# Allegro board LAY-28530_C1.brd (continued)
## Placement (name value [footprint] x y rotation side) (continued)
Q5  FDD4243  [TO252AA]  94.67 105.84 90 top
Q6  FDD4243  [TO252AA]  82.35 105.2 0 top
Q7  NTMD6N02R2  [SO8]  175.57 89.33 270 top
Q8  MMBT4401L  [SOT23]  175.19 43.36 180 top
Q9  MMBT4401L  [SOT23]  179 43.36 180 top
Q10  MMBT4401L  [SOT23]  203.76 31.93 180 top
Q11  MMBT4401L  [SOT23]  207.7 31.93 180 top
Q12  MMBT4401L  [SOT23]  199.57 21 0 top
Q13  MMBT4401L  [SOT23]  197.92 12.62 180 top
Q14  MMBT4401L  [SOT23]  211.89 146.61 0 bottom
Q15  MMBT4401L  [SOT23]  206.69 146.61 0 bottom
Q16  MMBT4401L  [SOT23]  194.75 141.15 180 bottom
Q17  MMBT3906L  [SOT23]  76.49 121.21 0 bottom
Q18  MMBT3904LT1G  [SOT23]  80.07 121.21 0 bottom
Q19  NTMD6N02R2  [SO8]  70.03 102.54 90 top
Q20  MMBT4401L  [SOT23]  71.56 109.14 0 top
Q21  NTMD6N02R2  [SO8]  175.19 100.38 90 bottom
Q22  NTMD6N02R2  [SO8]  175.57 87.81 90 bottom
Q23  IRLML6346TRPbF  [SOT23-40X40]  77.27 51.36 270 top
Q24  MMBT4401L  [SOT23]  179 43.36 180 bottom
Q25  MMBT4401L  [SOT23]  175.19 43.36 180 bottom
Q28  MMBT4401L  [SOT23]  158.68 8.18 270 bottom
Q29  MMBT4401L  [SOT23]  199.57 30.27 0 top
Q30  MMBT4401L  [SOT23]  199.57 26.08 0 top
R1  29.4K  [RC0603_OV]  80.57 153.97 180 bottom
R2  3.01K  [RC0603_OV]  80.57 155.75 0 bottom
R3  38.3K  [RC0603_OV]  84.26 158.8 90 top
R4  100K  [RC0603_OV]  86.04 158.8 90 top
R5  10.0K  [RC0603_OV]  68.38 155.75 0 top
R6  4.7K  [RC0402_25]  171.38 154.23 180 top
R7  4.7K  [RC0402_25]  171.38 153.08 180 top
R8  4.7K  [RC0402_25]  207.7 149.78 270 top
R9  1K  [RC0603_OV]  211.13 149.53 0 top
R10  18.2K  [RC0603_OV]  198.81 149.4 180 top
R11  51.1K  [RC0603_OV]  202.11 149.4 180 top
R13  0.033  [RC1206_OV]  84.26 147.62 180 top
R14  0  [RC0603_OV]  88.45 148.13 270 top
R15  10K  [RC0603_OV]  206.94 143.56 180 top
R16  1K  [RC0603_OV]  210.11 143.56 0 top
R17  4.7K  [RC0402_25]  213.42 143.56 180 top
R19  26.7K  [RC0603_OV]  191.06 141.91 0 top
R20  2.0K  [RC0603_OV]  159.44 141.02 270 top
R21  0  [RC0603_OV]  161.22 141.02 90 top
R22  0  [RC0603_OV]  193.99 141.02 90 top
R23  1K  [RC0603_OV]  195.64 141.02 90 top
R24  100  [RC0603_OV]  163.38 140.89 90 top
R25  1K  [RC0603_OV]  191.06 140.26 0 top
R26  100  [RC0603_OV]  143.19 139.88 90 top
R27  0  [RC0603_OV]  97.34 137.59 180 top
R28  2.49K  [RC0603_OV]  130.36 137.46 180 top
R29  4.7K  [RC0402_25]  196.53 137.46 180 top
R30  2.49K  [RC0603_OV]  109.78 137.34 180 top
R31  330  [RC0603_OV]  113.72 137.34 90 top
R32  330  [RC0603_OV]  138.87 137.34 90 top
R33  0  [RC0402_25]  193.35 136.95 180 top
R34  330  [RC0603_OV]  94.67 136.83 90 top
R35  330  [RC0603_OV]  118.42 136.19 0 top
R36  10.0K  [RC0603_OV]  196.78 136.07 180 top
R37  0  [RC0603_OV]  97.34 135.94 180 top
R38  0  [RC0402_25]  193.35 135.81 180 top
R39  1.0M  [RC0603_OV]  129.85 135.05 90 top
R40  1.0M  [RC0603_OV]  108.39 134.92 90 top
R42  15  [RC1206_OV]  92.64 124.13 90 bottom
R43  0  [RC0603_OV]  118.42 134.67 180 top
R44  36K  [RC0402_25]  196.4 134.54 180 top
R45  0  [RC0402_25]  196.4 133.4 0 top
R46  0  [RC0603_OV]  118.42 133.14 180 top
R47  0  [RC0603_OV]  81.84 115.36 180 bottom
R48  56K  [RC0402_25]  196.4 132.26 180 top
R49  0  [RC0402_25]  96.7 132 180 top
R50  33  [RC0603_OV]  108.77 131.62 0 top
R51  4.7K  [RC0603_OV]  118.93 131.37 0 top
R52  0  [RC0603_OV]  171.38 131.11 180 top
R53  0  [RC0402_25]  96.7 130.99 180 top
R54  0  [RC0402_25]  196.4 130.99 0 top
R55  0  [RC0402_25]  96.7 129.97 180 top
R56  4.7K  [RC0603_OV]  118.93 129.84 180 top
R57  4.7K  [RC0603_OV]  113.21 129.46 0 top
R58  4.7K  [RC0603_OV]  132.14 129.33 0 top
R59  0  [RC0402_25]  98.1 129.08 180 top
R60  100K  [RC0603_OV]  193.35 128.83 0 top
R61  0  [RC0603_OV]  81.84 113.46 180 bottom
R62  0  [RC0402_25]  98.1 128.06 180 top
R63  4.7K  [RC0603_OV]  113.21 127.81 180 top
R64  0  [RC0603_OV]  132.14 127.81 0 top
R65  0  [RC0402_25]  101.28 127.3 270 top
R66  0  [RC0603_OV]  108.77 127.05 0 top
R67  4.7K  [RC0603_OV]  124.14 126.79 270 top
R68  4.7K  [RC0603_OV]  122.48 126.67 90 top
R69  4.7K  [RC0603_OV]  120.83 126.67 270 top
R70  4.7K  [RC0603_OV]  113.21 126.16 0 top
R71  0  [RC0603_OV]  132.14 126.16 0 top
R72  4.7K  [RC0603_OV]  98.1 125.65 90 top
R73  4.7K  [RC0603_OV]  99.75 125.65 90 top
R74  0  [RC0603_OV]  108.77 125.4 0 top
R75  4.7K  [RC0603_OV]  174.17 125.14 270 top
R76  4.7K  [RC0603_OV]  174.17 121.59 90 top
R77  14K  [RC0402_25]  210.88 121.08 0 top
R78  100K  [RC0603_OV]  205.54 119.56 90 top
R79  100K  [RC0603_OV]  207.19 119.56 90 top
R80  0  [RC0402_25]  210.88 118.67 0 top
R81  24K  [RC0603_OV]  211.13 117.14 0 top
R82  10K  [RC0603_OV]  211.13 115.49 180 top
R83  100K  [RC0603_OV]  140.65 114.48 180 top
R84  1K  [RC0603_OV]  111.31 105.2 270 top
R85  191K  [RC0402_25]  134.17 114.09 0 top
R86  4.7K  [RC0402_25]  108.13 115.62 270 top
R87  20K  [RC0402_25]  134.17 112.95 180 top
R88  20K  [RC0402_25]  140.9 112.95 180 top
R89  100K  [RC0603_OV]  210.62 112.57 180 top
R90  0  [RC0402_25]  210.37 111.17 0 top
R91  10.0  [RC0402_25]  202.75 111.05 0 top
R92  0  [RC0402_25]  210.37 110.03 180 top
R93  100K  [RC0603_OV]  210.62 108.38 0 top
R94  10.0K  [RC0603_OV]  103.18 106.22 90 top
R95  10.0K  [RC0603_OV]  133.79 104.06 270 top
R96  10.0K  [RC0603_OV]  135.31 104.06 90 top
R97  10.0K  [RC0603_OV]  79.3 97.97 180 top
R98  330  [RC0402_25]  178.87 98.09 270 top
R99  22  [RC0603_OV]  166.3 96.82 0 top
R100  0.001  [RC1206_OV]  100.39 93.77 0 top
R101  330  [RC0402_25]  180.27 95.43 90 top
R102  2.2K  [RC0603_OV]  75.62 95.93 270 top
R104  10K  [RC0603_OV]  94.04 84.76 0 top
R105  10K  [RC0603_OV]  97.08 84.76 180 top
R106  33  [RC0603_OV]  103.05 85.77 0 top
R107  49.9  [RC0603_OV]  105.97 85.77 0 top
R108  33  [RC0603_OV]  103.05 83.61 0 top
R109  49.9  [RC0603_OV]  105.97 83.61 0 top
R110  33  [RC0603_OV]  103.05 81.71 0 top
R111  49.9  [RC0603_OV]  105.97 81.71 0 top
R112  1M  [RC0402_25]  93.53 80.31 270 top
R113  33  [RC0603_OV]  103.05 79.55 0 top
R114  49.9  [RC0603_OV]  105.97 79.55 0 top
R115  10K  [RC0603_OV]  87.69 77.9 0 top
R116  33  [RC0603_OV]  103.05 77.77 0 top
R117  49.9  [RC0603_OV]  106.1 77.77 0 top
R118  10K  [RC0603_OV]  91.75 77.65 0 top
R119  10K  [RC0603_OV]  87.69 76.25 0 top
R120  10K  [RC0603_OV]  91.75 75.74 0 top
R121  33  [RC0603_OV]  103.05 75.61 0 top
R122  49.9  [RC0603_OV]  106.1 75.61 0 top
R123  33  [RC0603_OV]  97.59 74.98 270 top
R124  33  [RC0603_OV]  99.37 74.98 270 top
R125  10K  [RC0603_OV]  87.69 74.6 0 top
R126  10K  [RC0603_OV]  87.69 72.82 0 top
R127  30.9K  [RC0603_OV]  95.56 67.49 270 top
R128  1M  [RC0402_25]  92.64 67.23 90 top
R129  60.4K  [RC0402_25]  85.02 65.2 180 top
R130  4.7K  [RC0402_25]  212.78 62.41 180 top
R131  4.7K  [RC0402_25]  212.78 61.26 180 top
R132  330  [RC0603_OV]  212.53 59.74 0 top
R133  1K  [RC0603_OV]  212.53 58.09 0 top
R134  24.9K  [RC0402_25]  109.28 57.96 0 top
R135  10K  [RC0603_OV]  205.29 57.45 180 bottom
R136  1K  [RC0603_OV]  212.53 56.44 0 top
R137  100K  [RC0603_OV]  109.53 56.56 0 top
R138  10K  [RC0603_OV]  205.29 55.67 180 bottom
R139  1K  [RC0603_OV]  212.53 54.79 0 top
R140  10K  [RC0603_OV]  205.29 53.9 180 bottom
R141  1K  [RC0603_OV]  212.53 53.13 0 top
R142  1K  [RC0603_OV]  176.21 47.67 270 top
R143  10K  [RC0603_OV]  177.98 47.67 90 top
R144  1K  [RC0603_OV]  180.02 47.67 90 top
R145  10.0K  [RC0603_OV]  98.74 47.29 0 top
R146  100K  [RC0603_OV]  106.48 46.91 270 top
R147  4.7K  [RC0402_25]  98.48 45.9 180 top
R148  412K  [RC0402_25]  90.35 43.99 270 top
R149  1M  [RC0402_25]  89.21 43.99 90 top
R150  1K  [RC0603_OV]  175.95 39.8 180 top
R151  412K  [RC0402_25]  108.51 39.42 0 top
R152  1M  [RC0402_25]  108.51 38.15 180 top
R153  1K  [RC0603_OV]  205.54 35.23 180 top
R154  1K  [RC0603_OV]  209.48 35.23 180 top
R155  1K  [RC0603_OV]  189.54 33.7 90 top
R156  1K  [RC0603_OV]  191.19 33.7 90 top
R157  10K  [RC0603_OV]  175.44 33.58 270 top
R158  10K  [RC0603_OV]  177.48 33.58 270 top
R159  10K  [RC0603_OV]  183.06 33.58 270 top
R160  10K  [RC0603_OV]  184.71 33.58 270 top
R161  10K  [RC0603_OV]  195.13 33.58 270 top
R162  10K  [RC0603_OV]  196.91 33.58 270 top
R163  1K  [RC0603_OV]  207.45 27.48 180 top
R164  0  [RC0402_25]  207.19 29.13 180 top
R165  1K  [RC0603_OV]  203.38 21.13 180 top
R166  39  [RC0402_25]  169.86 26.72 180 top
R167  10K  [RC0603_OV]  90.1 26.59 90 top
R168  39  [RC0402_25]  169.86 25.7 180 top
R169  39  [RC0402_25]  169.86 24.69 180 top
R170  39  [RC0402_25]  169.86 23.67 180 top
R171  39  [RC0402_25]  169.86 22.65 180 top
R172  4.7K  [RC0402_25]  203.26 23.04 0 top
R173  39  [RC0402_25]  169.86 21.64 180 top
R174  39  [RC0402_25]  169.86 20.62 180 top
R175  39  [RC0402_25]  169.86 19.61 180 top
R176  39  [RC0402_25]  169.86 18.59 180 top
R177  39  [RC0402_25]  169.86 17.57 180 top
R178  39  [RC0402_25]  169.86 16.56 180 top
R179  1K  [RC0603_OV]  198.94 16.18 90 top
R180  39  [RC0402_25]  169.86 15.16 180 top
R181  39  [RC0402_25]  169.86 14.15 180 top
R182  39  [RC0402_25]  169.86 13.13 180 top
R183  39  [RC0402_25]  169.86 12.11 180 top
R184  4.7K  [RC0402_25]  200.72 11.99 90 top
R185  30.9  [RC0603_OV]  90.1 155.62 270 bottom
R186  10K  [RC0603_OV]  78.29 151.31 90 bottom
R187  20  [RC0603_OV]  78.16 145.72 270 bottom
R188  20K  [RC0402_25]  78.16 143.05 90 bottom
R189  383K  [RC0402_25]  77.65 148.64 0 bottom
R190  12K  [RC0603_OV]  88.19 150.92 0 bottom
R191  2.2K  [RC0603_OV]  85.27 150.8 180 bottom
R192  14.0K  [RC0603_OV]  81.59 147.88 270 bottom
R193  1K  [RC0603_OV]  206.94 149.91 180 bottom
R194  1K  [RC0603_OV]  211.64 149.4 0 bottom
R195  150  [RC1206_OV]  83.5 141.27 0 bottom
R196  100  [RC0603_OV]  73.21 136.7 180 bottom
R197  4.7K  [RC0402_25]  211.38 144.07 0 bottom
R198  10K  [RC0603_OV]  190.94 142.92 180 bottom
R199  0  [RC0603_OV]  190.94 141.27 0 bottom
R200  4.7K  [RC0402_25]  161.09 141.27 90 bottom
R201  100  [RC0603_OV]  159.44 141.02 270 bottom
R202  1K  [RC0603_OV]  176.33 138.61 90 bottom
R203  0  [RC0603_OV]  169.98 134.16 90 bottom
R204  10K  [RC0603_OV]  72.83 114.73 0 bottom
R205  0  [RC0603_OV]  163.96 133.27 90 bottom
R206  0  [RC0603_OV]  166.68 132.89 180 bottom
R207  4.7K  [RC0603_OV]  95.81 132.51 0 bottom
R208  15  [RC0603_OV]  73.59 121.46 270 bottom
R209  0  [RC0603_OV]  150.93 131.87 0 bottom
R210  4.7K  [RC0603_OV]  95.81 130.99 0 bottom
R211  0  [RC0603_OV]  172.65 130.73 0 bottom
R212  4.7K  [RC0603_OV]  150.17 130.35 180 bottom
R213  4.7K  [RC0603_OV]  132.14 129.59 180 bottom
R214  4.7K  [RC0603_OV]  95.81 129.46 0 bottom
R215  0  [RC0603_OV]  172.65 128.95 0 bottom
R216  4.7K  [RC0603_OV]  146.49 128.32 180 bottom
R217  4.7K  [RC0603_OV]  97.97 127.94 180 bottom
R218  4.7K  [RC0603_OV]  131.63 127.81 0 bottom
R219  0  [RC0603_OV]  172.65 127.3 0 bottom
R220  0  [RC0603_OV]  122.1 127.18 0 bottom
R221  0  [RC0603_OV]  101.4 125.91 0 bottom
R222  4.7K  [RC0603_OV]  172.65 125.65 180 bottom
R223  0  [RC0603_OV]  125.15 125.65 0 bottom
R224  0  [RC0603_OV]  122.1 125.65 0 bottom
R225  0  [RC0603_OV]  103.82 125.02 90 bottom
R226  0  [RC0603_OV]  101.4 124.25 0 bottom
R227  180  [RC0402_25]  172.4 124.13 0 bottom
R228  0  [RC0603_OV]  169.73 122.98 270 bottom
R229  330  [RC0402_25]  172.4 122.86 0 bottom
R230  1K  [RC0603_OV]  71.94 95.68 270 top
R231  4.7K  [RC0402_25]  73.84 95.93 90 top
R232  10.0K  [RC0603_OV]  67.37 95.81 270 top
R233  162K  [RC0402_25]  206.94 112.82 0 bottom
R234  10.0K  [RC0603_OV]  69.4 95.81 270 top
R235  10.0K  [RC0603_OV]  68.13 108.76 90 top
R236  10.0K  [RC0603_OV]  74.61 109.52 270 top
R237  4.7K  [RC0402_25]  200.21 101.14 270 bottom
R238  4.7K  [RC0402_25]  192.59 101.14 270 bottom
R239  4.7K  [RC0402_25]  191.32 97.58 90 bottom
R240  4.7K  [RC0402_25]  171.38 97.08 0 bottom
R241  10K  [RC0603_OV]  177.73 93.52 270 bottom
R242  10K  [RC0603_OV]  173.28 93.52 270 bottom
R243  4.7K  [RC0402_25]  194.75 89.84 180 bottom
R244  4.7K  [RC0402_25]  210.88 87.42 180 bottom
R245  20K  [RC0402_25]  205.42 87.42 180 bottom
R246  0  [RC0805_OV]  77.27 47.8 180 top
R247  10K  [RC0603_OV]  77.02 56.82 180 top
R248  10K  [RC0603_OV]  77.02 54.66 180 top
R249  10K  [RC0603_OV]  74.22 46.66 270 top
R250  4.7K  [RC0402_25]  210.88 86.15 180 bottom
R251  20K  [RC0402_25]  205.42 86.15 180 bottom
R252  4.7K  [RC0402_25]  210.88 84.88 180 bottom
R253  20K  [RC0402_25]  205.42 84.88 180 bottom
R254  4.7K  [RC0402_25]  210.88 83.61 180 bottom
R255  20K  [RC0402_25]  205.42 83.61 180 bottom
R256  4.7K  [RC0402_25]  210.88 82.34 180 bottom
R257  20K  [RC0402_25]  205.42 82.34 180 bottom
R258  10K  [RC0603_OV]  173.03 81.58 0 bottom
R259  4.7K  [RC0402_25]  121.09 81.2 0 bottom
R260  4.7K  [RC0402_25]  118.29 81.2 180 bottom
R261  4.7K  [RC0402_25]  210.88 81.07 180 bottom
R262  20K  [RC0402_25]  205.42 81.07 180 bottom
R263  2.2  [RC0402_25]  93.78 80.95 270 bottom
R264  4.7K  [RC0402_25]  121.09 80.06 0 bottom
R265  4.7K  [RC0402_25]  118.29 80.06 180 bottom
R266  1K  [RC0603_OV]  173.03 79.93 0 bottom
R267  4.7K  [RC0402_25]  210.88 79.8 180 bottom
R268  20K  [RC0402_25]  205.42 79.8 180 bottom
R269  4.7K  [RC0402_25]  164.01 79.8 180 bottom
R270  4.7K  [RC0402_25]  164.01 78.79 180 bottom
R271  49.9  [RC0402_25]  149.66 78.66 90 bottom
R272  4.7K  [RC0402_25]  148.52 78.66 270 bottom
R273  5.1  [RC0402_25]  147.25 78.66 270 bottom
R274  5.1  [RC0402_25]  142.8 78.66 270 bottom
R275  4.7K  [RC0402_25]  210.88 78.53 180 bottom
R276  20K  [RC0402_25]  205.42 78.53 180 bottom
R277  4.7K  [RC0603_OV]  135.57 78.53 90 bottom
R278  4.7K  [RC0603_OV]  133.66 78.53 270 bottom
R279  1.5K  [RC0603_OV]  131.88 78.53 270 bottom
R280  4.7K  [RC0402_25]  138.11 78.28 270 bottom
R281  4.7K  [RC0402_25]  133.15 74.47 270 bottom
R282  49.9  [RC0603_OV]  156.65 77.26 180 bottom
R283  1K  [RC0603_OV]  163.76 76.5 180 bottom
R284  49.9  [RC0402_25]  144.84 75.99 270 bottom
R285  10  [RC0402_25]  138.74 75.99 270 bottom
R286  10  [RC0402_25]  137.47 75.99 270 bottom
R287  10  [RC0402_25]  136.33 75.99 270 bottom
R288  10  [RC0402_25]  134.55 75.99 270 bottom
R289  4.7K  [RC0402_25]  128.58 76.63 180 bottom
R290  4.7K  [RC0402_25]  164.01 62.91 0 bottom
R291  20K  [RC0402_25]  179.89 91.23 270 top
R292  20K  [RC0402_25]  164.01 75.11 0 bottom
R293  4.7K  [RC0402_25]  210.88 74.85 180 bottom
R294  0.033  [RC0603_OV]  113.98 74.85 180 bottom
R295  10  [RC0402_25]  131.96 74.55 270 bottom
R296  10  [RC0402_25]  130.74 74.47 270 bottom
R297  1K  [RC0603_OV]  156.65 74.47 0 bottom
R298  10K  [RC0603_OV]  145.47 74.22 0 bottom
R299  20K  [RC0402_25]  164.01 74.09 0 bottom
R300  4.7K  [RC0402_25]  210.88 73.58 180 bottom
R301  4.7K  [RC0402_25]  198.05 73.58 90 bottom
R302  20K  [RC0402_25]  164.01 73.07 0 bottom
R303  4.7K  [RC0402_25]  210.88 72.31 180 bottom
R304  20K  [RC0402_25]  164.01 72.06 0 bottom
R305  0  [RC0402_25]  114.48 72.06 180 bottom
R307  4.7K  [RC0402_25]  210.88 71.04 180 bottom
R308  20K  [RC0402_25]  164.01 71.04 0 bottom
R309  200  [RC0603_OV]  122.36 70.91 180 bottom
R310  20K  [RC0402_25]  164.01 70.03 180 bottom
R311  4.7K  [RC0402_25]  210.88 69.77 180 bottom
R312  4.7K  [RC0402_25]  164.01 69.01 0 bottom
R313  4.7K  [RC0402_25]  210.88 68.5 180 bottom
R314  4.7K  [RC0402_25]  164.01 67.99 0 bottom
R315  4.7K  [RC0402_25]  197.41 71.17 90 bottom
R317  4.7K  [RC0402_25]  164.01 66.98 0 bottom
R318  4.7K  [RC0402_25]  210.88 65.96 180 bottom
R319  4.7K  [RC0402_25]  164.01 65.96 0 bottom
R320  10K  [RC0603_OV]  86.92 65.71 0 bottom
R321  20K  [RC0402_25]  164.01 64.95 180 bottom
R323  1K  [RC0603_OV]  160.84 64.56 90 bottom
R324  20K  [RC0402_25]  164.01 63.93 180 bottom
R325  4.7K  [RC0402_25]  158.93 61.9 0 bottom
R326  0.001  [RC1206_OV]  107.5 61.64 0 bottom
R327  10K  [RC0603_OV]  102.16 58.21 0 bottom
R328  4.7K  [RC0402_25]  159.06 57.96 180 bottom
R329  698  [RC0402_25]  115.88 56.44 180 bottom
R330  0.033  [RC0603_OV]  116.26 54.79 180 bottom
R331  5.1  [RC0402_25]  159.06 53.64 180 bottom
R333  33  [RC0603_OV]  60.25 76.38 270 top
R334  49.9  [RC0603_OV]  60.25 73.33 270 top
R335  475  [RC0603_OV]  69.27 79.68 0 top
R336  0  [RC0402_25]  116.52 52.75 180 bottom
R337  698  [RC0402_25]  159.06 52.5 0 bottom
R338  300  [RC0402_25]  141.28 51.74 90 bottom
R339  300  [RC0402_25]  140.26 51.74 90 bottom
R340  300  [RC0402_25]  139.25 51.74 90 bottom
R341  300  [RC0402_25]  138.11 51.74 90 bottom
R342  162  [RC0402_25]  137.09 51.74 90 bottom
R343  162  [RC0402_25]  135.95 51.74 90 bottom
R345  49.9  [RC0603_OV]  66.22 76.25 270 top
R346  330  [RC0402_25]  159.06 51.36 0 bottom
R347  33  [RC0603_OV]  62.29 76.38 270 top
R348  49.9  [RC0603_OV]  62.29 73.33 270 top
R349  698  [RC0402_25]  159.06 50.21 0 bottom
R350  49.9  [RC0603_OV]  64.06 76.25 270 top
R351  33  [RC0603_OV]  62.67 86.41 90 top
R352  49.9  [RC0603_OV]  62.67 89.46 90 top
R353  4.7K  [RC0402_25]  159.06 49.07 180 bottom
R354  0  [RC0402_25]  159.06 47.8 180 bottom
R355  475  [RC0603_OV]  69.27 83.61 0 top
R356  1K  [RC0603_OV]  175.19 47.67 270 bottom
R357  33  [RC0603_OV]  60.64 86.41 90 top
R358  49.9  [RC0603_OV]  60.64 89.46 90 top
R359  60.4K  [RC0402_25]  95.94 45.64 180 bottom
R360  10K  [RC0603_OV]  202.75 45.51 90 bottom
R361  60.4K  [RC0402_25]  107.75 44.5 270 bottom
R362  10K  [RC0603_OV]  197.67 41.32 270 bottom
R363  10K  [RC0603_OV]  195.13 41.32 270 bottom
R364  10K  [RC0603_OV]  192.59 41.32 270 bottom
R365  10K  [RC0603_OV]  190.05 41.32 270 bottom
R366  10K  [RC0603_OV]  187.51 41.32 270 bottom
R367  1K  [RC0603_OV]  180.02 39.16 90 bottom
R368  1K  [RC0603_OV]  176.21 39.16 90 bottom
R369  10K  [RC0603_OV]  202.75 38.91 90 bottom
R370  10  [RC0603_OV]  200.21 38.91 270 bottom
R371  240  [RC0402_25]  165.66 27.35 270 bottom
R372  240  [RC0402_25]  151.57 27.23 270 bottom
R373  240  [RC0402_25]  123.75 27.23 270 bottom
R374  240  [RC0402_25]  137.72 27.1 270 bottom
R375  39  [RC0402_25]  169.86 26.72 180 bottom
R376  39  [RC0402_25]  169.86 25.7 180 bottom
R377  39  [RC0402_25]  169.86 24.69 180 bottom
R378  39  [RC0402_25]  169.86 23.67 180 bottom
R379  39  [RC0402_25]  160.97 23.54 0 bottom
R380  39  [RC0402_25]  169.86 22.65 180 bottom
R381  39  [RC0402_25]  160.97 22.4 180 bottom
R382  39  [RC0402_25]  169.86 21.64 180 bottom
R383  39  [RC0402_25]  169.86 20.62 180 bottom
R384  39  [RC0402_25]  169.86 19.61 180 bottom
R385  39  [RC0402_25]  169.86 18.59 180 bottom
R386  39  [RC0402_25]  169.86 17.57 180 bottom
R387  39  [RC0402_25]  169.86 16.56 180 bottom
R388  39  [RC0402_25]  169.86 15.16 180 bottom
R389  39  [RC0402_25]  169.86 14.15 180 bottom
R390  10K  [RC0603_OV]  165.92 14.02 180 bottom
R391  39  [RC0402_25]  169.86 13.13 180 bottom
R392  100  [RC0603_OV]  132.26 10.97 270 bottom
R393  100  [RC0603_OV]  130.61 10.97 270 bottom
R394  330  [RC0603_OV]  124.01 10.97 270 bottom
R395  330  [RC0603_OV]  121.47 10.97 270 bottom
R396  330  [RC0603_OV]  112.07 9.19 0 bottom
R397  330  [RC0603_OV]  143.06 8.05 90 bottom
R398  330  [RC0603_OV]  150.93 7.92 270 bottom
R399  330  [RC0603_OV]  170.24 2.97 0 bottom
R400  330  [RC0603_OV]  155.63 7.92 270 bottom
R401  330  [RC0603_OV]  112.2 5.38 0 bottom
R402  4.7K  [RC0402_25]  192.46 68.37 0 bottom
R404  39  [RC0402_25]  134.3 81.71 270 bottom
R415  0  [RC0402_25]  33.71 58.72 270 bottom
R416  0  [RC0402_25]  32.57 58.72 270 bottom
R417  0  [RC0402_25]  51.11 137.84 180 bottom
R418  0  [RC0402_25]  51.11 136.57 180 bottom
R420  1.5K  [RC0603_OV]  122.99 76.88 90 bottom
R421  1.5K  [RC0603_OV]  128.71 79.3 90 bottom
R422  1.5K  [RC0603_OV]  121.21 76.88 90 bottom
R423  1.5K  [RC0603_OV]  126.68 76.88 270 bottom
R424  1.5K  [RC0603_OV]  124.77 76.88 270 bottom
R425  1.5K  [RC0603_OV]  124.77 73.45 270 bottom
R426  1.5K  [RC0603_OV]  126.68 73.45 270 bottom
R431  0  [RC0402_25]  129.47 74.47 270 bottom
R432  0  [RC0402_25]  128.2 74.47 270 bottom
R433  412K  [RC0402_25]  31.04 67.74 270 top
R434  1M  [RC0402_25]  18.34 79.3 90 top
R435  60.4K  [RC0402_25]  16.82 89.33 90 top
R436  10.0K  [RC0603_OV]  14.92 93.9 90 top
R437  4.7K  [RC0402_25]  15.68 89.33 270 top
R439  383K  [RC0402_25]  32.31 67.74 270 top
R440  240K  [RC0402_25]  34.85 67.74 270 top
R441  274K  [RC0402_25]  33.58 67.74 270 top
R444  10  [RC0603_OV]  77.02 62.66 0 top
R445  10  [RC0603_OV]  77.02 64.31 0 top
R446  10  [RC0603_OV]  80.57 87.42 180 top
R447  10  [RC0603_OV]  80.57 89.08 180 top
R448  0  [RC0402_25]  68.51 89.08 0 top
R449  0  [RC0402_25]  68.51 87.81 0 top
R450  0  [RC0402_25]  65.08 64.44 0 top
R451  0  [RC0402_25]  65.08 63.04 0 top
R452  0  [RC0603_OV]  155.38 164.67 270 bottom
R453  0  [RC0603_OV]  153.09 164.51 270 bottom
R454  0  [RC0603_OV]  150.93 164.51 270 bottom
R455  0  [RC0603_OV]  148.52 164.69 270 bottom
R456  0  [RC0603_OV]  92.51 152.7 90 bottom
R457  0  [RC0603_OV]  103.18 152.7 90 bottom
R458  0  [RC0603_OV]  92.51 156.64 270 bottom
R459  0  [RC0603_OV]  103.18 156.77 270 bottom
R460  1K  [RC0603_OV]  203.26 28.12 180 top
R461  1K  [RC0603_OV]  203.26 26.21 0 top
R466  1K  [RC0603_OV]  158.3 93.9 270 bottom
R467  10K  [RC0603_OV]  196.14 62.66 0 bottom
R468  10K  [RC0603_OV]  159.31 56.56 0 bottom
R469  1M  [RC0402_25]  41.33 89.33 180 top
R470  60.4K  [RC0402_25]  31.3 87.93 180 top
R471  10.0K  [RC0603_OV]  28.89 93.9 90 top
R472  4.7K  [RC0402_25]  31.3 86.41 0 top
R473  412K  [RC0402_25]  32.7 95.93 180 top
R474  240K  [RC0402_25]  32.7 92.12 180 top
R475  274K  [RC0402_25]  32.7 93.39 180 top
R476  383K  [RC0402_25]  32.7 94.66 180 top
SW1  218-8LPST  [SW_DIP16_8POS_SM]  206.69 82.98 270 top
SW2  218-8LPST  [SW_DIP16_8POS_SM]  206.69 70.41 270 top
SW3  218-8LPST  [SW_DIP16_8POS_SM]  205.66 57.61 270 top
SW4  TL1105NF160Q  [SW_4P_7P1X15P8]  212.73 158.61 180 top
T1  PE-68386NL  [XFMR6_2P54_SM]  76.51 128.83 270 bottom
T2  PA2467NL  [XFMR10_2P5_13X14_SM]  81.84 128.95 90 top
TP1  35 MIL  [TESTPOINT_35MIL]  89.46 156.13 270 top
TP2  35 MIL  [TESTPOINT_35MIL]  90.48 149.4 270 top
TP3  35 MIL  [TESTPOINT_35MIL]  90.48 148 270 top
TP5  35 MIL  [TESTPOINT_35MIL]  110.55 83.11 0 top
TP7  35 MIL  [TESTPOINT_35MIL]  110.55 81.58 0 top
TP8  35 MIL  [TESTPOINT_35MIL]  109.15 80.19 0 top
TP9  35 MIL  [TESTPOINT_35MIL]  110.55 80.06 0 top
TP10  35 MIL  [TESTPOINT_35MIL]  109.15 78.79 0 top
TP11  35 MIL  [TESTPOINT_35MIL]  110.55 78.41 0 top
TP12  35 MIL  [TESTPOINT_35MIL]  96.45 65.58 0 top
TP13  35 MIL  [TESTPOINT_35MIL]  171.51 55.04 0 top
TP15  35 MIL  [TESTPOINT_35MIL]  172.9 51.23 0 top
TP16  35 MIL  [TESTPOINT_35MIL]  174.3 51.23 0 top
TP17  35 MIL  [TESTPOINT_35MIL]  88.7 45.9 0 top
TP18  35 MIL  [TESTPOINT_35MIL]  99.04 23.98 0 top
TP19  35 MIL  [TESTPOINT_35MIL]  100.39 23.92 0 top
TP24  35 MIL  [TESTPOINT_35MIL]  127.18 69.14 180 bottom
TP28  35 MIL  [TESTPOINT_35MIL]  127.18 71.3 270 bottom
TP30  35 MIL  [TESTPOINT_35MIL]  128.71 69.14 270 bottom
TP31  35 MIL  [TESTPOINT_35MIL]  152.33 61.26 180 bottom
TP32  35 MIL  [TESTPOINT_35MIL]  153.73 61.01 180 bottom
TP33  35 MIL  [TESTPOINT_35MIL]  156.65 60.25 180 bottom
TP34  35 MIL  [TESTPOINT_35MIL]  155.12 60.75 180 bottom
TP35  35 MIL  [TESTPOINT_35MIL]  158.04 59.74 180 bottom
TP36  35 MIL  [TESTPOINT_35MIL]  151.19 59.23 270 bottom
TP37  35 MIL  [TESTPOINT_35MIL]  130.74 58.85 270 bottom
TP38  35 MIL  [TESTPOINT_35MIL]  164.14 56.06 180 bottom
TP39  35 MIL  [TESTPOINT_35MIL]  162.24 57.83 180 bottom
TP40  35 MIL  [TESTPOINT_35MIL]  164.14 57.83 180 bottom
TP41  35 MIL  [TESTPOINT_35MIL]  162.49 54.28 270 bottom
TP42  35 MIL  [TESTPOINT_35MIL]  124.9 56.56 270 bottom
TP43  35 MIL  [TESTPOINT_35MIL]  123.25 56.56 180 bottom
TP44  35 MIL  [TESTPOINT_35MIL]  164.14 54.28 270 bottom
TP45  35 MIL  [TESTPOINT_35MIL]  159.19 60.63 180 bottom
TP46  35 MIL  [TESTPOINT_35MIL]  150.42 60.75 180 bottom
TP47  35 MIL  [TESTPOINT_35MIL]  165.79 56.06 180 bottom
TP48  35 MIL  [TESTPOINT_35MIL]  160.08 78.53 180 bottom
TP49  35 MIL  [TESTPOINT_35MIL]  159.82 74.98 180 bottom
TP50  35 MIL  [TESTPOINT_35MIL]  87.31 22.27 0 top
TP51  35 MIL  [TESTPOINT_35MIL]  142.04 75.23 180 bottom
TP55  35 MIL  [TESTPOINT_35MIL]  165.66 50.98 180 bottom
TP56  35 MIL  [TESTPOINT_35MIL]  165.54 52.88 180 bottom
TP57  35 MIL  [TESTPOINT_35MIL]  87.31 24.05 0 top
TP58  35 MIL  [TESTPOINT_35MIL]  17.46 81.07 270 top
TP59  35 MIL  [TESTPOINT_35MIL]  139.5 78.79 180 bottom
TP60  35 MIL  [TESTPOINT_35MIL]  141.41 78.79 180 bottom
TP61  35 MIL  [TESTPOINT_35MIL]  142.04 77.01 180 bottom
TP62  35 MIL  [TESTPOINT_35MIL]  39.55 88.44 0 top
U1  LTC4269CDKD-1  [DFN32_0P4_4X7_EP]  86.8 152.83 270 top
U2  SP3232  [SSOP16]  177.6 151.56 180 top
U3  MAX811  [SOT143-25X60]  206.69 146.61 270 top
U4  MAX1558H  [TDFN10_0P5_3P1X3P1]  190.94 145.08 0 top
U5  RTL8211FS  [QFN_48_0P4_6X6MM]  103.43 133.78 270 top
U6  RTL8211FS  [QFN_48_0P4_6X6MM]  124.64 133.78 270 top
U7  LTC3600  [DFN12_3X3_0P45]  192.46 133.27 180 top
U8  AQR105-B1  [BGA324_1MM_19X19MM_C019S]  158.93 129.08 0 top
U9  LTC3605A  [QFN24_4X4MM]  205.67 114.48 90 top
U10  DS1339U-33+  [USOP-8]  108.26 110.92 90 top
U11  LT3021EDH  [EDFN16_0P5_5X5_3P45X4P1]  137.09 108.89 270 top
U12  LT3021EDH  [EDFN16_0P5_5X5_3P45X4P1]  143.69 108.89 270 top
U13  M24256-BWDW6TP  [TSSOP8]  114.48 109.14 90 top
U14  S25FL512S  [SOIC16_1P27_7P5X10P3]  195.76 99.36 270 top
U15  IDTQS3VH257PA  [TSSOP16]  182.17 87.93 270 bottom
U16  S34MS04G200BHI000  [VFBGA63_0P8_9X11]  191.83 86.66 270 top
U19  5P49V5901A616NLGI  [QFN24_0P5_4X4_EP2P2]  97.47 80.19 0 top
U20  S29GL01GS11TFIV10  [TSOP56_0P5_18_4X14_IN]  188.27 72.18 180 top
U21  T1023 + SKT 525 BGA + 3001295  [SKT_BGA525_0P8_58P6SQ_SM]  141 64.01 270 top
U22  LT8612  [QFN28_3X6_0P5]  89.08 63.8 0 top
U23  SN74LVC1G86  [SOT-23-5]  196.65 61.77 270 top
U24  SN74LVC1G86  [SOT-23-5]  196.65 57.83 270 top
U25  SN74LVC16373ADGGR  [TSSOP48-11X70]  181.92 57.58 90 top
U26  LT3021EDH  [EDFN16_0P5_5X5_3P45X4P1]  104.7 55.29 180 top
U27  SN74LVC1G86  [SOT-23-5]  196.65 53.9 270 top
U28  LT8612  [QFN28_3X6_0P5]  93.91 48.05 180 top
U29  LT8612  [QFN28_3X6_0P5]  105.34 42.59 270 top
U30  RCLAMP0524J  [SLP2710P8]  180.65 30.15 270 top
U31  RCLAMP0524J  [SLP2710P8]  192.33 30.15 270 top
U32  IDTQS3VH257PA  [TSSOP16]  181.16 24.56 180 top
U33  IDTQS3VH257PA  [TSSOP16]  191.45 24.56 180 top
U34  MT40A512M8  [FBGA78_0P8_9X11P5]  119.15 22.1 0 top
U35  MT40A512M8  [FBGA78_0P8_9X11P5]  133.12 22.1 0 top
U36  MT40A512M8  [FBGA78_0P8_9X11P5]  147.09 22.1 0 top
U37  MT40A512M8  [FBGA78_0P8_9X11P5]  161.06 22.1 0 top
U38  PC34VR500V4ES  [QFN56_0P5_8X8_EP4P1X4P4]  93.53 19.86 0 top
U39  S40410081B1B1W000  [FBGA153_0P5_11P5X13]  187.25 10.46 270 top
U40  SRV05-4  [SOT23_S6]  197.03 153.85 270 bottom
U41  MX25V4006E  [SO8_1P27_4X5]  145.34 133.14 90 bottom
U42  INA220AIDGST  [MSOP_10_0P5_3X3]  70.03 62.66 0 top
U43  85102AGILF  [TSSOP16]  63.05 81.33 180 top
U44  TXBN0304RSVR  [PQFN16_0P4_2P65X1P85]  192.46 47.17 270 bottom
U45  LT8612  [QFN28_3X6_0P5]  15.3 84.5 270 top
U47  INA220AIDGST  [MSOP_10_0P5_3X3]  73.34 87.55 0 top
U48  TCA6408APWR  [TSSOP16]  159.06 100.12 90 top
U49  LT8612  [QFN28_3X6_0P5]  36.12 86.28 0 top
Y1  25MHZ  [XTLOSC4_3P2X2P5MM_SM]  134.3 136.07 90 top
Y2  25MHZ  [XTLOSC4_3P2X2P5MM_SM]  114.74 133.53 90 top
Y3  50Mhz  [XTAL4_3P3X2P6_SM_FL]  175.32 133.27 270 top
Y4  32.768KHz  [XTL2_TF_SM]  107.75 101.27 90 top
Y5  25MHz  [XTAL4_3P3X2P6_SM_FL]  88.45 81.07 0 top

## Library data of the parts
BH1-BH4 = MOUNT_HOLE
BT1 = BATTERY_SKT_3V
C1 C3-C8 C30 C37 C41 C50 C51 C56 C57 C67 C75 C84 C100 C104 C113 C119-C121 C123 C128 C131 C134 C135 C137-C140 C144-C148 C150-C152 C156 C157 C159-C162 C166 C169 C182 C184 C193 C199-C206 C214 C215 C217 C218 C221 C222 C228 C230 C234-C238 C240 C245 C246 C276 C279-C282 C285 C287 C290 C294-C296 C301-C303 C305 C309 C313 C314 C317 C318 C323 C325 C332 C344 C355 C365 C366 C377 C381 C386 C391 C403 C405 C408 C409 C417 C427 C429 C444 C461 C466 C469 C474 C477 C481 C485-C487 C525 C535 C545 C550 C557 C558 C570 C581 C582 C593-C595 C599 C600 C605 C606 C609 C633 C637 C644 C645 C652 C656 = CAP_NP: signal model: DEFAULT_CAPACITOR_100000pF_2_1
C2 = CAP_POL: signal model: DEFAULT_CAPACITOR_1e+07pF_2_1
C9 C20 C22-C24 C61 C603 C604 C607 C608 = CAP_NP: signal model: DEFAULT_CAPACITOR_100.000000pF_2_1
C10 C13 C15 C17 C34 C54 C58 C68-C70 C94 C95 C108 C185 C330 C467 C634 C639 C643 C648 C653 C658 = MOT_CAP: signal model: DEFAULT_CAPACITOR_4.7e+07pF_2_1
C11 C167 C168 C171 C172 C178 = CAP_NP: signal model: DEFAULT_CAPACITOR_1000pF_2_1
C12 C62 C63 C91 C97-C99 C102 C110 C111 C115 C283 C284 C292 C299 C304 C312 C315 C316 C319 C320 C327 C367-C369 C376 C395 C410 C460 C462 C468 C470-C473 C476 C482 C569 C591 C635 C654 = CAP_NP: signal model: DEFAULT_CAPACITOR_1e+07pF_2_1
C14 C35 C47 C49 C55 C59 C64 C65 C76-C78 C90 C107 C118 = CAP_POL: signal model: DEFAULT_CAPACITOR_1e+08pF_2_1
C16 C18 C27 C601 C602 = CAP_NP: signal model: DEFAULT_CAPACITOR_470.000000pF_2_1
C19 C28 C38 C46 C48 C229 C233 C241 C247 C250 C251 C329 C465 C544 C551 C556 C563 C579 C590 C592 C596-C598 = CAP_NP: signal model: DEFAULT_CAPACITOR_4.7e+06pF_2_1
C21 C88 C103 C105 C208 C631 C650 = CAP_NP: signal model: DEFAULT_CAPACITOR_2200pF_2_1
C25 C26 C31 C33 C36 C44 = CAP_NP: signal model: DEFAULT_CAPACITOR_18.000000pF_2_1
C29 C39 C72-C74 C79 C92 C96 C101 C116 C122 C130 C132 C133 C136 C143 C153-C155 C158 C164 C165 C611 C636 C655 = CAP_NP: signal model: DEFAULT_CAPACITOR_2.2e+07pF_2_1
C32 = CAP_NP: signal model: DEFAULT_CAPACITOR_68.000000pF_2_1
C40 C89 C93 C125-C127 C141 C149 C175 C181 C188 C198 C333 C342 C345 C370 C380 C397-C400 C449 C455 C478 C480 C524 C534 C564-C568 C575-C578 C580 C583-C589 C630 C638 C649 C657 = CAP_NP: signal model: DEFAULT_CAPACITOR_1e+06pF_2_1
C42 C45 C331 = CAP_NP: signal model: DEFAULT_CAPACITOR_22.000000pF_2_1
C43 C53 C87 C106 C109 C632 C651 = CAP_NP: signal model: DEFAULT_CAPACITOR_10.000000pF_2_1
C52 = CAP_NP: signal model: DEFAULT_CAPACITOR_220.000000pF_2_1
C60 C66 C80 C286 C306-C308 C321 C322 C324 C428 C439 C440 C456-C458 C623 C624 C627 C628 C646 C647 = CAP_NP: tolerance: 10%; signal model: DEFAULT_CAPACITOR_100000pF_2_1
C71 C142 C163 C176 C179 C183 C187 C191 C192 C194-C197 C207 C209-C213 C216 C219 C220 C223-C227 C231 C232 C239 C242-C244 C248 C249 C252-C268 C270-C272 C335 C336 C356 C357 C401 C402 C422 C423 C451 C452 = CAP_NP: signal model: DEFAULT_CAPACITOR_2.2e+06pF_2_1
C81 C189 C190 C269 C273-C275 C277 C278 C288 C289 C293 C298 C310 = CAP_NP: signal model: DEFAULT_CAPACITOR_10000pF_2_1
C82 C112 C114 C117 C297 C337-C341 C343 C346-C354 C359-C364 C371-C375 C378 C379 C382-C385 C387-C390 C392-C394 C396 C406 C407 C412-C416 C418-C420 C424 C426 C430-C433 C436-C438 C441 C445-C447 C454 C459 C475 C479 C483 C484 C488-C523 C526-C533 C536-C543 C546-C549 C552-C555 C559-C562 C571-C574 = CAP_NP: Tolerance: TOLERANCE; User Part Number: 150-75429; signal model: DEFAULT_CAPACITOR_100000pF_2_1
C85 C86 = CAP_NP: signal model: DEFAULT_CAPACITOR_2.000000pF_2_1
C124 = CAP_NP: signal model: DEFAULT_CAPACITOR_220000pF_2_1
C129 = CAP_NP: signal model: DEFAULT_CAPACITOR_470000pF_2_1
C170 = CAP_POL: signal model: DEFAULT_CAPACITOR_2.2e+07pF_2_1
C173 C174 = CAP_NP: signal model: DEFAULT_CAPACITOR_33.000000pF_2_1
C177 = CAP_NP: signal model: DEFAULT_CAPACITOR_4700pF_2_1
C180 = CAP_NP: signal model: DEFAULT_CAPACITOR_620.000000pF_2_1
C186 = CAP_NP: signal model: DEFAULT_CAPACITOR_47.000000pF_2_1
C300 C326 C443 C463 C622 C626 = CAP_NP: tolerance: 20%; signal model: DEFAULT_CAPACITOR_2.2e+07pF_2_1
C311 C434 C435 C442 C453 = CAP_NP: Tolerance: TOLERANCE; User Part Number: 150-78890; signal model: DEFAULT_CAPACITOR_10000pF_2_1
C328 C334 C358 C404 C425 C450 C464 = CAP_NP: signal model: DEFAULT_CAPACITOR_3000pF_2_1
D1-D4 D7-D10 D19-D22 = DIODE_SCHTKY
D5 = DIODE
D6 = ZDIODE
D11 D15-D18 = LED
D12-D14 = LED_DUAL_SEP2_YG
D23 = DIODE_TVS
D24 = DIODE_SOT23
D25 = DIODE_SCH_BAT54
F1 = FUSE_RESETTABLE
FL1 FL2 = NFM18PC225B1A3
J1 = PHONEJACK-3
J2 = USB_A
J3 = CON_RJ45_19P
J4 J5 = RJ45_LED_22P
J6 J10 J11 = CONN_HDR_2X1
J7 = HDR-1X7
J8 J9 J12 J14 J18-J21 J23 J26 = CONN_HDR_3X1
J13 = HTST-108-01-L-DV
J16 = CONN_SDCARD_1X13_F_511
J24 = CON_RJ45_16P
J25 J27 = CONN_HDR_4X2
L1 L2 L27-L29 = BEAD_FERRITE: signal model: DEFAULT_RESISTOR_120.000000OHM_2_1
L3 L5-L7 = INDUCTOR: tolerance: 25%; signal model: DEFAULT_RESISTOR_1000.000000OHM_2_1
L4 = DLW43
L8 L12 = BEAD: signal model: DEFAULT_RESISTOR_600.000000OHM_2_1
L9 = INDUCTOR: signal model: DEFAULT_INDUCTOR_10000nH_2_1
L10 = INDUCTOR: signal model: DEFAULT_RESISTOR_600.000000OHM_2_1
L11 L14 L15 L18-L20 L30 L31 = INDUCTOR: signal model: DEFAULT_INDUCTOR_2200nH_2_1
L13 = INDUCTOR: signal model: DEFAULT_INDUCTOR_330.000000nH_2_1
L16 L22 = INDUCTOR: signal model: DEFAULT_INDUCTOR_1000nH_2_1
L17 = BEAD
L21 L23 L24 = INDUCTOR: signal model: DEFAULT_INDUCTOR_1500nH_2_1
L25 L26 = BEAD: signal model: DEFAULT_RESISTOR_220.000000OHM_2_1
P1 = RJ45-8
P2 P3 = MINI_PCI_LATCH_52P
Q1 Q8-Q16 Q18 Q20 Q24 Q25 Q28-Q30 = NPN
Q2 Q3 = MOSFET_N_8P
Q4-Q6 = P_MOS
Q7 Q19 Q21 Q22 = MMDF4N01HD
Q17 = PNP
Q23 = MOSFET_N
R1 = RES: signal model: DEFAULT_RESISTOR_29400OHM_2_1
R2 = RES: signal model: DEFAULT_RESISTOR_3010OHM_2_1
R3 = RES: signal model: DEFAULT_RESISTOR_38300OHM_2_1
R4 R60 R78 R79 R83 R89 R93 R137 R146 = RES: signal model: DEFAULT_RESISTOR_100000OHM_2_1
R5 = RES: tolerance: 1%; signal model: DEFAULT_RESISTOR_10000OHM_2_1
R6-R8 R17 R29 R86 R147 R197 R200 R231 R259 R260 R264 R265 R269 R270 R272 R280 R281 R289 R328 R353 R437 R472 = RES: tolerance: 5%; signal model: DEFAULT_RESISTOR_4700OHM_2_1
R9 R16 R23 R25 R84 R133 R136 R139 R141 R142 R144 R150 R153-R156 R163 R165 R179 R193 R194 R202 R230 R266 R283 R297 R323 R356 R367 R368 R460 R461 R466 = RES: signal model: DEFAULT_RESISTOR_1000.000000OHM_2_1
R10 = RES: signal model: DEFAULT_RESISTOR_18200OHM_2_1
R11 = RES: signal model: DEFAULT_RESISTOR_51100OHM_2_1
R13 R294 R330 = RES: signal model: DEFAULT_RESISTOR_0.033OHM_2_1
R14 R21 R22 R27 R33 R37-R40 R43 R45-R47 R49 R52-R55 R59 R61 R62 R64-R66 R71 R74 R80 R90 R92 R100 R112 R128 R149 R152 R164 R199 R203 R205 R206 R209 R211 R215 R219-R221 R223-R226 R228 R246 R305 R326 R336 R354 R415-R418 R431 R432 R434 R448-R459 R469 = RES: signal model: DEFAULT_RESISTOR_0.001OHM_2_1
R15 R36 R82 R94-R97 R104 R105 R115 R118-R120 R125 R126 R135 R138 R140 R143 R145 R157-R162 R167 R186 R198 R204 R232 R234-R236 R241 R242 R247-R249 R258 R298 R320 R327 R360 R362-R366 R369 R390 R436 R467 R468 R471 = RES: signal model: DEFAULT_RESISTOR_10000OHM_2_1
R19 = RES: signal model: DEFAULT_RESISTOR_26700OHM_2_1
R20 = RES: signal model: DEFAULT_RESISTOR_2000OHM_2_1
R24 R26 R196 R201 R392 R393 = RES: signal model: DEFAULT_RESISTOR_100.000000OHM_2_1
R28 R30 = RES: signal model: DEFAULT_RESISTOR_2490OHM_2_1
R31 R32 R34 R35 R98 R101 R132 R229 R346 R394-R396 R401 = RES: signal model: DEFAULT_RESISTOR_330.000000OHM_2_1
R42 R208 = RES: signal model: DEFAULT_RESISTOR_15.000000OHM_2_1
R44 = RES: signal model: DEFAULT_RESISTOR_36000OHM_2_1
R48 = RES: signal model: DEFAULT_RESISTOR_56000OHM_2_1
R50 R99 R282 = RES: signal model: RES_RC0603_OV_DISCRETE_470-75_7_22
R51 R56-R58 R63 R67-R70 R72 R73 R75 R76 R130 R131 R172 R184 R207 R210 R212-R214 R216-R218 R222 R237-R240 R243 R244 R250 R252 R254 R256 R261 R267 R275 R277 R278 R290 R293 R300 R301 R303 R307 R311-R315 R317-R319 R325 R402 = RES: signal model: DEFAULT_RESISTOR_4700OHM_2_1
R77 R192 = RES: signal model: DEFAULT_RESISTOR_14000OHM_2_1
R81 = RES: signal model: DEFAULT_RESISTOR_24000OHM_2_1
R85 = RES: signal model: DEFAULT_RESISTOR_191000OHM_2_1
R87 R88 R188 R245 R251 R253 R255 R257 R262 R268 R276 R291 R292 R299 R302 R304 R308 R310 R321 R324 = RES: signal model: DEFAULT_RESISTOR_20000OHM_2_1
R91 R285-R288 R295 R296 R370 R444-R447 = RES: signal model: DEFAULT_RESISTOR_10.000000OHM_2_1
R102 R191 = RES: signal model: DEFAULT_RESISTOR_2200OHM_2_1
R106 R108 R110 R113 R116 R121 R123 R124 R333 R347 R351 R357 = RES: signal model: DEFAULT_RESISTOR_33.000000OHM_2_1
R107 R109 R111 R114 R117 R122 R271 R284 R334 R345 R348 R350 R352 R358 = RES: signal model: DEFAULT_RESISTOR_49.900000OHM_2_1
R127 = RES: signal model: DEFAULT_RESISTOR_30900OHM_2_1
R129 R359 R361 R435 R470 = RES: signal model: DEFAULT_RESISTOR_60400OHM_2_1
R134 = RES: signal model: DEFAULT_RESISTOR_24900OHM_2_1
R148 R151 R433 R473 = RES: signal model: DEFAULT_RESISTOR_412000OHM_2_1
R166 R168-R171 R173-R178 R180-R183 R375-R389 R391 R404 = RES: signal model: DEFAULT_RESISTOR_39.000000OHM_2_1
R185 = RES: signal model: DEFAULT_RESISTOR_30.900000OHM_2_1
R187 = RES: signal model: DEFAULT_RESISTOR_20.000000OHM_2_1
R189 R439 R476 = RES: signal model: DEFAULT_RESISTOR_383000OHM_2_1
R190 = RES: signal model: DEFAULT_RESISTOR_12000OHM_2_1
R195 = RES: signal model: DEFAULT_RESISTOR_150.000000OHM_2_1
R227 = RES: signal model: DEFAULT_RESISTOR_180.000000OHM_2_1
R233 = RES: signal model: DEFAULT_RESISTOR_162000OHM_2_1
R263 = RES: signal model: DEFAULT_RESISTOR_2.200000OHM_2_1
R273 R274 R331 = RES: signal model: DEFAULT_RESISTOR_5.100000OHM_2_1
R279 R420-R426 = RES: signal model: DEFAULT_RESISTOR_1500OHM_2_1
R309 = RES: signal model: DEFAULT_RESISTOR_200.000000OHM_2_1
R329 R337 R349 = RES: signal model: DEFAULT_RESISTOR_698.000000OHM_2_1
R335 R355 = RES: signal model: DEFAULT_RESISTOR_475.000000OHM_2_1
R338-R341 = RES: signal model: DEFAULT_RESISTOR_300.000000OHM_2_1
R342 R343 = RES: signal model: DEFAULT_RESISTOR_162.000000OHM_2_1
R371-R374 = RES: signal model: DEFAULT_RESISTOR_240.000000OHM_2_1
R397-R400 = RES: tolerance: 1%; signal model: DEFAULT_RESISTOR_330.000000OHM_2_1
R440 R474 = RES: signal model: DEFAULT_RESISTOR_240000OHM_2_1
R441 R475 = RES: signal model: DEFAULT_RESISTOR_274000OHM_2_1
SW1-SW3 = SW_DIP_8
SW4 = SW_TACT-SPST-2_SM1
T1 = PE-68386_6P
T2 = PA2467_10P
TP1-TP3 TP5 TP7-TP13 TP15-TP19 TP24 TP28 TP30-TP51 TP55-TP62 = Test pad: Tolerance: TOLERANCE; User Part Number: 510-75219
U1 = LTC4269-1_32P_EP
U2 = SP3232E
U3 = MAX811
U4 = MAX1558H_TDFN_10P
U5 U6 = RTL8211_48P
U7 = LTC3600_12P_DFN_EP
U8 = AQR105_BGA324
U9 = LTC3605A_24P_QFN_EP
U10 = DS1339
U11 U12 U26 = LT3021
U13 = M24256
U14 = S25FL256S_SOIC_16P
U15 U32 U33 = IDTQS3VH257_16P
U16 = S34MS04G200BH_BGA63P
U19 = IDT5P49V5901_24P
U20 = S29GL01GS_56P
U21 = T1023_BGA_525P
U22 U28 U29 U45 U49 = LT8612_28P_QFN_EP
U23 U24 U27 = SN74LVC
U25 = SN74LVC16373A_48P
U30 U31 = RCLAMP0524J
U34-U37 = MT40A512M8
U38 = MC34VR500V1ES_56P
U39 = S40410161B1_FBGA_153P
U40 = SRV05-4
U41 = MX25V4006E_8P
U42 U47 = INA220AIDGST
U43 = 85102AGI_TSSOP_16P
U44 = TXBN0304_QFN16
U48 = TCA6408A_16P
Y1 Y2 = CRYSTAL_JXS63
Y3 Y5 = XTAL_13Y
Y4 = XTAL

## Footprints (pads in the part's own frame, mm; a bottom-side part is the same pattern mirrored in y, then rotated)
BGA324_1MM_19X19MM_C019S
  round 0.483 smd: A1(-8.499,8.499) A2(-7.501,8.499) A3(-6.5,8.499) A4(-5.499,8.499) A5(-4.501,8.499) A6(-3.5,8.499) A7(-2.499,8.499) A8(-1.501,8.499) A9(-0.5,8.499) A10(0.5,8.499) A11(1.501,8.499) A12(2.499,8.499) A13(3.5,8.499) A14(4.501,8.499) A15(5.499,8.499) A16(6.5,8.499) A17(7.501,8.499) A18(8.499,8.499) B1(-8.499,7.501) B2(-7.501,7.501) B3(-6.5,7.501) B4(-5.499,7.501) B5(-4.501,7.501) B6(-3.5,7.501) B7(-2.499,7.501) B8(-1.501,7.501) B9(-0.5,7.501) B10(0.5,7.501) B11(1.501,7.501) B12(2.499,7.501) B13(3.5,7.501) B14(4.501,7.501) B15(5.499,7.501) B16(6.5,7.501) B17(7.501,7.501) B18(8.499,7.501) C1(-8.499,6.5) C2(-7.501,6.5) C3(-6.5,6.5) C4(-5.499,6.5) C5(-4.501,6.5) C6(-3.5,6.5) C7(-2.499,6.5) C8(-1.501,6.5) C9(-0.5,6.5) C10(0.5,6.5) C11(1.501,6.5) C12(2.499,6.5) C13(3.5,6.5) C14(4.501,6.5) C15(5.499,6.5) C16(6.5,6.5) C17(7.501,6.5) C18(8.499,6.5) D1(-8.499,5.499) D2(-7.501,5.499) D3(-6.5,5.499) D4(-5.499,5.499) D5(-4.501,5.499) D6(-3.5,5.499) D7(-2.499,5.499) D8(-1.501,5.499) D9(-0.5,5.499) D10(0.5,5.499) D11(1.501,5.499) D12(2.499,5.499) D13(3.5,5.499) D14(4.501,5.499) D15(5.499,5.499) D16(6.5,5.499) D17(7.501,5.499) D18(8.499,5.499) E1(-8.499,4.501) E2(-7.501,4.501) E3(-6.5,4.501) E4(-5.499,4.501) E5(-4.501,4.501) E6(-3.5,4.501) E7(-2.499,4.501) E8(-1.501,4.501) E9(-0.5,4.501) E10(0.5,4.501) E11(1.501,4.501) E12(2.499,4.501) E13(3.5,4.501) E14(4.501,4.501) E15(5.499,4.501) E16(6.5,4.501) E17(7.501,4.501) E18(8.499,4.501) F1(-8.499,3.5) F2(-7.501,3.5) F3(-6.5,3.5) F4(-5.499,3.5) F5(-4.501,3.5) F6(-3.5,3.5) F7(-2.499,3.5) F8(-1.501,3.5) F9(-0.5,3.5) F10(0.5,3.5) F11(1.501,3.5) F12(2.499,3.5) F13(3.5,3.5) F14(4.501,3.5) F15(5.499,3.5) F16(6.5,3.5) F17(7.501,3.5) F18(8.499,3.5) G1(-8.499,2.499) G2(-7.501,2.499) G3(-6.5,2.499) G4(-5.499,2.499) G5(-4.501,2.499) G6(-3.5,2.499) G7(-2.499,2.499) G8(-1.501,2.499) G9(-0.5,2.499) G10(0.5,2.499) G11(1.501,2.499) G12(2.499,2.499) G13(3.5,2.499) G14(4.501,2.499) G15(5.499,2.499) G16(6.5,2.499) G17(7.501,2.499) G18(8.499,2.499) H1(-8.499,1.501) H2(-7.501,1.501) H3(-6.5,1.501) H4(-5.499,1.501) H5(-4.501,1.501) H6(-3.5,1.501) H7(-2.499,1.501) H8(-1.501,1.501) H9(-0.5,1.501) H10(0.5,1.501) H11(1.501,1.501) H12(2.499,1.501) H13(3.5,1.501) H14(4.501,1.501) H15(5.499,1.501) H16(6.5,1.501) H17(7.501,1.501) H18(8.499,1.501) J1(-8.499,0.5) J2(-7.501,0.5) J3(-6.5,0.5) J4(-5.499,0.5) J5(-4.501,0.5) J6(-3.5,0.5) J7(-2.499,0.5) J8(-1.501,0.5) J9(-0.5,0.5) J10(0.5,0.5) J11(1.501,0.5) J12(2.499,0.5) J13(3.5,0.5) J14(4.501,0.5) J15(5.499,0.5) J16(6.5,0.5) J17(7.501,0.5) J18(8.499,0.5) K1(-8.499,-0.5) K2(-7.501,-0.5) K3(-6.5,-0.5) K4(-5.499,-0.5) K5(-4.501,-0.5) K6(-3.5,-0.5) K7(-2.499,-0.5) K8(-1.501,-0.5) K9(-0.5,-0.5) K10(0.5,-0.5) K11(1.501,-0.5) K12(2.499,-0.5) K13(3.5,-0.5) K14(4.501,-0.5) K15(5.499,-0.5) K16(6.5,-0.5) K17(7.501,-0.5) K18(8.499,-0.5) L1(-8.499,-1.501) L2(-7.501,-1.501) L3(-6.5,-1.501) L4(-5.499,-1.501) L5(-4.501,-1.501) L6(-3.5,-1.501) L7(-2.499,-1.501) L8(-1.501,-1.501) L9(-0.5,-1.501) L10(0.5,-1.501) L11(1.501,-1.501) L12(2.499,-1.501) L13(3.5,-1.501) L14(4.501,-1.501) L15(5.499,-1.501) L16(6.5,-1.501) L17(7.501,-1.501) L18(8.499,-1.501) M1(-8.499,-2.499) M2(-7.501,-2.499) M3(-6.5,-2.499) M4(-5.499,-2.499) M5(-4.501,-2.499) M6(-3.5,-2.499) M7(-2.499,-2.499) M8(-1.501,-2.499) M9(-0.5,-2.499) M10(0.5,-2.499) M11(1.501,-2.499) M12(2.499,-2.499) M13(3.5,-2.499) M14(4.501,-2.499) M15(5.499,-2.499) M16(6.5,-2.499) M17(7.501,-2.499) M18(8.499,-2.499) N1(-8.499,-3.5) N2(-7.501,-3.5) N3(-6.5,-3.5) N4(-5.499,-3.5) N5(-4.501,-3.5) N6(-3.5,-3.5) N7(-2.499,-3.5) N8(-1.501,-3.5) N9(-0.5,-3.5) N10(0.5,-3.5) N11(1.501,-3.5) N12(2.499,-3.5) N13(3.5,-3.5) N14(4.501,-3.5) N15(5.499,-3.5) N16(6.5,-3.5) N17(7.501,-3.5) N18(8.499,-3.5) P1(-8.499,-4.501) P2(-7.501,-4.501) P3(-6.5,-4.501) P4(-5.499,-4.501) P5(-4.501,-4.501) P6(-3.5,-4.501) P7(-2.499,-4.501) P8(-1.501,-4.501) P9(-0.5,-4.501) P10(0.5,-4.501) P11(1.501,-4.501) P12(2.499,-4.501) P13(3.5,-4.501) P14(4.501,-4.501) P15(5.499,-4.501) P16(6.5,-4.501) P17(7.501,-4.501) P18(8.499,-4.501) R1(-8.499,-5.499) R2(-7.501,-5.499) R3(-6.5,-5.499) R4(-5.499,-5.499) R5(-4.501,-5.499) R6(-3.5,-5.499) R7(-2.499,-5.499) R8(-1.501,-5.499) R9(-0.5,-5.499) R10(0.5,-5.499) R11(1.501,-5.499) R12(2.499,-5.499) R13(3.5,-5.499) R14(4.501,-5.499) R15(5.499,-5.499) R16(6.5,-5.499) R17(7.501,-5.499) R18(8.499,-5.499) T1(-8.499,-6.5) T2(-7.501,-6.5) T3(-6.5,-6.5) T4(-5.499,-6.5) T5(-4.501,-6.5) T6(-3.5,-6.5) T7(-2.499,-6.5) T8(-1.501,-6.5) T9(-0.5,-6.5) T10(0.5,-6.5) T11(1.501,-6.5) T12(2.499,-6.5) T13(3.5,-6.5) T14(4.501,-6.5) T15(5.499,-6.5) T16(6.5,-6.5) T17(7.501,-6.5) T18(8.499,-6.5) U1(-8.499,-7.501) U2(-7.501,-7.501) U3(-6.5,-7.501) U4(-5.499,-7.501) U5(-4.501,-7.501) U6(-3.5,-7.501) U7(-2.499,-7.501) U8(-1.501,-7.501) U9(-0.5,-7.501) U10(0.5,-7.501) U11(1.501,-7.501) U12(2.499,-7.501) U13(3.5,-7.501) U14(4.501,-7.501) U15(5.499,-7.501) U16(6.5,-7.501) U17(7.501,-7.501) U18(8.499,-7.501) V1(-8.499,-8.499) V2(-7.501,-8.499) V3(-6.5,-8.499) V4(-5.499,-8.499) V5(-4.501,-8.499) V6(-3.5,-8.499) V7(-2.499,-8.499) V8(-1.501,-8.499) V9(-0.5,-8.499) V10(0.5,-8.499) V11(1.501,-8.499) V12(2.499,-8.499) V13(3.5,-8.499) V14(4.501,-8.499) V15(5.499,-8.499) V16(6.5,-8.499) V17(7.501,-8.499) V18(8.499,-8.499)
CASE_F_8P5X8P5
  rect 4.191x2.108 smd: 1(-3.65,0) 2(3.65,0)
CC0201
  rect 0.47x0.381 smd: 1(-0.343,0) 2(0.343,0)
CC0402_25
  round 0.635 smd: 1(-0.508,0) 2(0.508,0)
CC0603_NFM18PC
  rect 0.61x0.61 smd: 1(-0.8,0) 3(0.8,0)
  rect 0.406x1.702 smd: 2(0,0)
CC0603_OV
  oval 0.889x1.143 smd: 1(-0.762,0) 2(0.762,0)
CC0805_OV
  oval 0.889x1.524 smd: 1(-0.965,0) 2(0.965,0)
CC1210
  rect 1.778x2.845 smd: 1(-1.397,0) 2(1.397,0)
CC1808_A
  rect 1.651x2.311 smd: 1(-1.925,0) 2(1.925,0)
CC1812
  rect 1.778x3.2 smd: 1(-2.515,0) 2(2.515,0)
CC1812_A
  rect 1.778x3.2 smd: 1(-2.515,0) 2(2.515,0)
CC3528-21
  rect 1.905x2.286 smd: 1(-1.714,0) 2(1.714,0)
CCE63X55
  rect 3.505x1.6 smd: 1(-2.7,0) 2(2.7,0)
CON3_PWR_JACK
  oval 4.013x1.549 hole 3.5x0.8: 1(0,0.201)
  oval 3.759x1.549 hole 2.997x0.787: 2(0,-6)
  oval 1.549x3.759 hole 0.787x2.997: 3(4.699,-3)
CON8_RJ45_1P02_16X17
  round 0.254 hole 3.251 unplated: (-9.921,-2.54) (2.779,-2.54)
  rect 1.499x1.499 hole 0.889: 1(0,0)
  round 1.499 hole 0.889: 2(-1.021,1.78) 3(-2.04,0) 4(-3.061,1.78) 5(-4.079,0) 6(-5.1,1.78) 7(-6.119,0) 8(-7.14,1.78)
  round 2.108 hole 1.6: 9(-11.709,0.889) 10(4.57,0.889)
CON16_RJ45_LED_80_TH_RA
  round 0.254 hole 3.251 unplated: (-9.9,-6.6) (-0.25,-6.6)
  rect 1.524x1.524 hole 0.889: 1(0,0)
  round 1.524 hole 0.889: 2(-2.03,0) 3(-4.06,0) 4(-6.09,0) 5(-8.12,0) 6(-10.15,0) 7(1.015,2.54) 8(-1.015,2.54) 9(-3.045,2.54) 10(-7.105,2.54) 11(-9.135,2.54) 12(-11.165,2.54) 13(-2.03,-4) 14(-4.06,-4) 15(-6.09,-4) 16(-8.12,-4)
  round 1.651 hole 1.143: 17(2.445,-10.41) 18(2.445,-12.95) 19(-12.595,-10.41) 20(-12.595,-12.95)
  round 2.184 hole 1.575: S1(-13.865,-6.6) S2(3.715,-6.6)
CON19_RJ-45_LED_80MIL_TH_RA
  round 0.254 hole 3.251 unplated: (0.254,6.604) (9.906,6.604)
  rect 1.524x1.524 hole 0.889: 1(0,0)
  round 1.524 hole 0.889: 2(2.032,0) 3(4.064,0) 4(6.096,0) 5(8.128,0) 6(10.16,0) 7(-1.016,-2.54) 8(1.016,-2.54) 9(3.048,-2.54) 10(7.112,-2.54) 11(9.144,-2.54) 12(11.176,-2.54) 13(0,-5.08) 14(8.128,-5.08) 15(10.16,-5.08)
  round 1.778 hole 1.143: 16(-2.438,10.414) 17(-2.438,12.954) 18(12.598,10.414) 19(12.598,12.954)
  round 2.184 hole 1.575: S1(-3.708,6.604) S2(13.868,6.604)
CON_2X26_0P8_SMT
  rect 2.311x3.2 smd: (-14.651,3.5) (14.651,3.5)
  round 0.254 hole 1.118 unplated: (-12.499,0)
  rect 5.791x5.791 hole 3.2: (-12.101,-48.049) (12.101,-48.049)
  round 0.254 hole 1.6 unplated: (12.499,0)
  rect 0.61x2.007 smd: 1(11.801,4.1) 2(11.399,-4.1) 3(11.001,4.1) 4(10.599,-4.1) 5(10.201,4.1) 6(9.799,-4.1) 7(9.4,4.1) 8(8.999,-4.1) 9(8.6,4.1) 10(8.199,-4.1) 11(7.8,4.1) 12(7.399,-4.1) 13(7,4.1) 14(6.599,-4.1) 15(6.2,4.1) 16(5.799,-4.1) 17(2.2,4.1) 18(1.801,-4.1) 19(1.399,4.1) 20(1.001,-4.1) 21(0.599,4.1) 22(0.201,-4.1) 23(-0.201,4.1) 24(-0.599,-4.1) 25(-1.001,4.1) 26(-1.399,-4.1) 27(-1.801,4.1) 28(-2.2,-4.1) 29(-2.601,4.1) 30(-3,-4.1) 31(-3.401,4.1) 32(-3.8,-4.1) 33(-4.201,4.1) 34(-4.6,-4.1) 35(-5.001,4.1) 36(-5.4,-4.1) 37(-5.799,4.1) 38(-6.2,-4.1) 39(-6.599,4.1) 40(-7,-4.1) 41(-7.399,4.1) 42(-7.8,-4.1) 43(-8.199,4.1) 44(-8.6,-4.1) 45(-8.999,4.1) 46(-9.4,-4.1) 47(-9.799,4.1) 48(-10.201,-4.1) 49(-10.599,4.1) 50(-11.001,-4.1) 51(-11.399,4.1) 52(-11.801,-4.1)
CON_RJ45_LED_20_TH
  round 0.254 hole 3.15 unplated: (-1.275,15.24) (11.425,15.24)
  rect 1.524x1.524 hole 0.889: 1(0,0)
  round 1.524 hole 0.889: 2(2.03,0) 3(4.059,0) 4(6.091,0) 5(8.12,0) 6(10.15,0) 7(-1.016,-2.54) 8(1.016,-2.54) 9(3.046,-2.54) 10(7.104,-2.54) 11(9.134,-2.54) 12(11.166,-2.54)
  oval 1.778x1.27 hole 0.889: 13(-0.516,7.12) 14(10.666,7.12) 15(-0.516,8.58) 16(10.666,8.58)
  round 1.651 hole 1.016: 17(-1.021,-5.08) 18(1.519,-5.08) 19(8.631,-5.08) 20(11.171,-5.08)
  round 2.235 hole 1.6: 21(-2.99,18.42) 22(13.139,18.42)
CON_SDCARD_13F_SM_RA_511
  round 0.254 hole 1.524 unplated: (-12.649,8.999) (11.549,8.999)
  rect 0.813x2.007 smd: 1(6.33,-15.499) 2(3.83,-15.499) 3(0.531,-15.499) 3A(2.131,-15.499) 4(-1.171,-15.499) 5(-3.67,-15.499) 6(-6.17,-15.499) 7(-8.6,-15.499) 8(-10.3,-15.499) 9(8.829,-15.499)
  rect 0.711x2.007 smd: 10(-13.79,-15.499)
  rect 1.803x2.413 smd: 11(13.551,5.7)
  rect 1.702x2.413 smd: 12(-13.8,6.901)
DFN12_3X3_0P45
  rect 0.686x0.254 smd: 1(-1.458,1.125) 2(-1.458,0.676) 3(-1.458,0.226) 4(-1.458,-0.226) 5(-1.458,-0.676) 6(-1.458,-1.125) 7(1.458,-1.125) 8(1.458,-0.676) 9(1.458,-0.226) 10(1.458,0.226) 11(1.458,0.676) 12(1.458,1.125)
  rect 1.651x2.388 smd: 13(0,0)
DFN32_0P4_4X7_EP
  rect 0.711x0.203 smd: 1(-1.9,3) 2(-1.9,2.601) 3(-1.9,2.2) 4(-1.9,1.801) 5(-1.9,1.399) 6(-1.9,1.001) 7(-1.9,0.599) 8(-1.9,0.201) 9(-1.9,-0.201) 10(-1.9,-0.599) 11(-1.9,-1.001) 12(-1.9,-1.399) 13(-1.9,-1.801) 14(-1.9,-2.2) 15(-1.9,-2.601) 16(-1.9,-3) 17(1.9,-3) 18(1.9,-2.601) 19(1.9,-2.2) 20(1.9,-1.801) 21(1.9,-1.399) 22(1.9,-1.001) 23(1.9,-0.599) 24(1.9,-0.201) 25(1.9,0.201) 26(1.9,0.599) 27(1.9,1.001) 28(1.9,1.399) 29(1.9,1.801) 30(1.9,2.2) 31(1.9,2.601) 32(1.9,3)
  rect 2.642x6.426 smd: 33(0,0)
EDFN16_0P5_5X5_3P45X4P1
  rect 0.711x0.305 smd: 1(-2.4,1.75) 2(-2.4,1.25) 3(-2.4,0.749) 4(-2.4,0.249) 5(-2.4,-0.249) 6(-2.4,-0.749) 7(-2.4,-1.25) 8(-2.4,-1.75) 9(2.4,-1.75) 10(2.4,-1.25) 11(2.4,-0.749) 12(2.4,-0.249) 13(2.4,0.249) 14(2.4,0.749) 15(2.4,1.25) 16(2.4,1.75)
  rect 3.454x4.115 smd: 17(0,0)
FBGA78_0P8_9X11P5
  round 0.356 smd: A1(-3.2,4.801) A2(-2.4,4.801) A3(-1.6,4.801) A7(1.6,4.801) A8(2.4,4.801) A9(3.2,4.801) B1(-3.2,4) B2(-2.4,4) B3(-1.6,4) B7(1.6,4) B8(2.4,4) B9(3.2,4) C1(-3.2,3.2) C2(-2.4,3.2) C3(-1.6,3.2) C7(1.6,3.2) C8(2.4,3.2) C9(3.2,3.2) D1(-3.2,2.4) D2(-2.4,2.4) D3(-1.6,2.4) D7(1.6,2.4) D8(2.4,2.4) D9(3.2,2.4) E1(-3.2,1.6) E2(-2.4,1.6) E3(-1.6,1.6) E7(1.6,1.6) E8(2.4,1.6) E9(3.2,1.6) F1(-3.2,0.8) F2(-2.4,0.8) F3(-1.6,0.8) F7(1.6,0.8) F8(2.4,0.8) F9(3.2,0.8) G1(-3.2,0) G2(-2.4,0) G3(-1.6,0) G7(1.6,0) G8(2.4,0) G9(3.2,0) H1(-3.2,-0.8) H2(-2.4,-0.8) H3(-1.6,-0.8) H7(1.6,-0.8) H8(2.4,-0.8) H9(3.2,-0.8) J1(-3.2,-1.6) J2(-2.4,-1.6) J3(-1.6,-1.6) J7(1.6,-1.6) J8(2.4,-1.6) J9(3.2,-1.6) K1(-3.2,-2.4) K2(-2.4,-2.4) K3(-1.6,-2.4) K7(1.6,-2.4) K8(2.4,-2.4) K9(3.2,-2.4) L1(-3.2,-3.2) L2(-2.4,-3.2) L3(-1.6,-3.2) L7(1.6,-3.2) L8(2.4,-3.2) L9(3.2,-3.2) M1(-3.2,-4) M2(-2.4,-4) M3(-1.6,-4) M7(1.6,-4) M8(2.4,-4) M9(3.2,-4) N1(-3.2,-4.801) N2(-2.4,-4.801) N3(-1.6,-4.801) N7(1.6,-4.801) N8(2.4,-4.801) N9(3.2,-4.801)
FBGA153_0P5_11P5X13
  round 0.254 smd: A1(-3.251,3.251) A2(-2.751,3.251) A3(-2.25,3.251) A4(-1.75,3.251) A5(-1.25,3.251) A6(-0.749,3.251) A7(-0.249,3.251) A8(0.249,3.251) A9(0.749,3.251) A10(1.25,3.251) A11(1.75,3.251) A12(2.25,3.251) A13(2.751,3.251) A14(3.251,3.251) B1(-3.251,2.751) B2(-2.751,2.751) B3(-2.25,2.751) B4(-1.75,2.751) B5(-1.25,2.751) B6(-0.749,2.751) B7(-0.249,2.751) B8(0.249,2.751) B9(0.749,2.751) B10(1.25,2.751) B11(1.75,2.751) B12(2.25,2.751) B13(2.751,2.751) B14(3.251,2.751) C1(-3.251,2.25) C2(-2.751,2.25) C3(-2.25,2.25) C4(-1.75,2.25) C5(-1.25,2.25) C6(-0.749,2.25) C7(-0.249,2.25) C8(0.249,2.25) C9(0.749,2.25) C10(1.25,2.25) C11(1.75,2.25) C12(2.25,2.25) C13(2.751,2.25) C14(3.251,2.25) D1(-3.251,1.75) D2(-2.751,1.75) D3(-2.25,1.75) D4(-1.75,1.75) D12(2.25,1.75) D13(2.751,1.75) D14(3.251,1.75) E1(-3.251,1.25) E2(-2.751,1.25) E3(-2.25,1.25) E5(-1.25,1.25) E6(-0.749,1.25) E7(-0.249,1.25) E8(0.249,1.25) E9(0.749,1.25) E10(1.25,1.25) E12(2.25,1.25) E13(2.751,1.25) E14(3.251,1.25) F1(-3.251,0.749) F2(-2.751,0.749) F3(-2.25,0.749) F5(-1.25,0.749) F10(1.25,0.749) F12(2.25,0.749) F13(2.751,0.749) F14(3.251,0.749) G1(-3.251,0.249) G2(-2.751,0.249) G3(-2.25,0.249) G5(-1.25,0.249) G10(1.25,0.249) G12(2.25,0.249) G13(2.751,0.249) G14(3.251,0.249) H1(-3.251,-0.249) H2(-2.751,-0.249) H3(-2.25,-0.249) H5(-1.25,-0.249) H10(1.25,-0.249) H12(2.25,-0.249) H13(2.751,-0.249) H14(3.251,-0.249) J1(-3.251,-0.749) J2(-2.751,-0.749) J3(-2.25,-0.749) J5(-1.25,-0.749) J10(1.25,-0.749) J12(2.25,-0.749) J13(2.751,-0.749) J14(3.251,-0.749) K1(-3.251,-1.25) K2(-2.751,-1.25) K3(-2.25,-1.25) K5(-1.25,-1.25) K6(-0.749,-1.25) K7(-0.249,-1.25) K8(0.249,-1.25) K9(0.749,-1.25) K10(1.25,-1.25) K12(2.25,-1.25) K13(2.751,-1.25) K14(3.251,-1.25) L1(-3.251,-1.75) L2(-2.751,-1.75) L3(-2.25,-1.75) L12(2.25,-1.75) L13(2.751,-1.75) L14(3.251,-1.75) M1(-3.251,-2.25) M2(-2.751,-2.25) M3(-2.25,-2.25) M4(-1.75,-2.25) M5(-1.25,-2.25) M6(-0.749,-2.25) M7(-0.249,-2.25) M8(0.249,-2.25) M9(0.749,-2.25) M10(1.25,-2.25) M11(1.75,-2.25) M12(2.25,-2.25) M13(2.751,-2.25) M14(3.251,-2.25) N1(-3.251,-2.751) N2(-2.751,-2.751) N3(-2.25,-2.751) N4(-1.75,-2.751) N5(-1.25,-2.751) N6(-0.749,-2.751) N7(-0.249,-2.751) N8(0.249,-2.751) N9(0.749,-2.751) N10(1.25,-2.751) N11(1.75,-2.751) N12(2.25,-2.751) N13(2.751,-2.751) N14(3.251,-2.751) P1(-3.251,-3.251) P2(-2.751,-3.251) P3(-2.25,-3.251) P4(-1.75,-3.251) P5(-1.25,-3.251) P6(-0.749,-3.251) P7(-0.249,-3.251) P8(0.249,-3.251) P9(0.749,-3.251) P10(1.25,-3.251) P11(1.75,-3.251) P12(2.25,-3.251) P13(2.751,-3.251) P14(3.251,-3.251)
